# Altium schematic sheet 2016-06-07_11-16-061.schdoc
size 405 x 220 mm; SheetNumber: 1; SheetTotal: 1
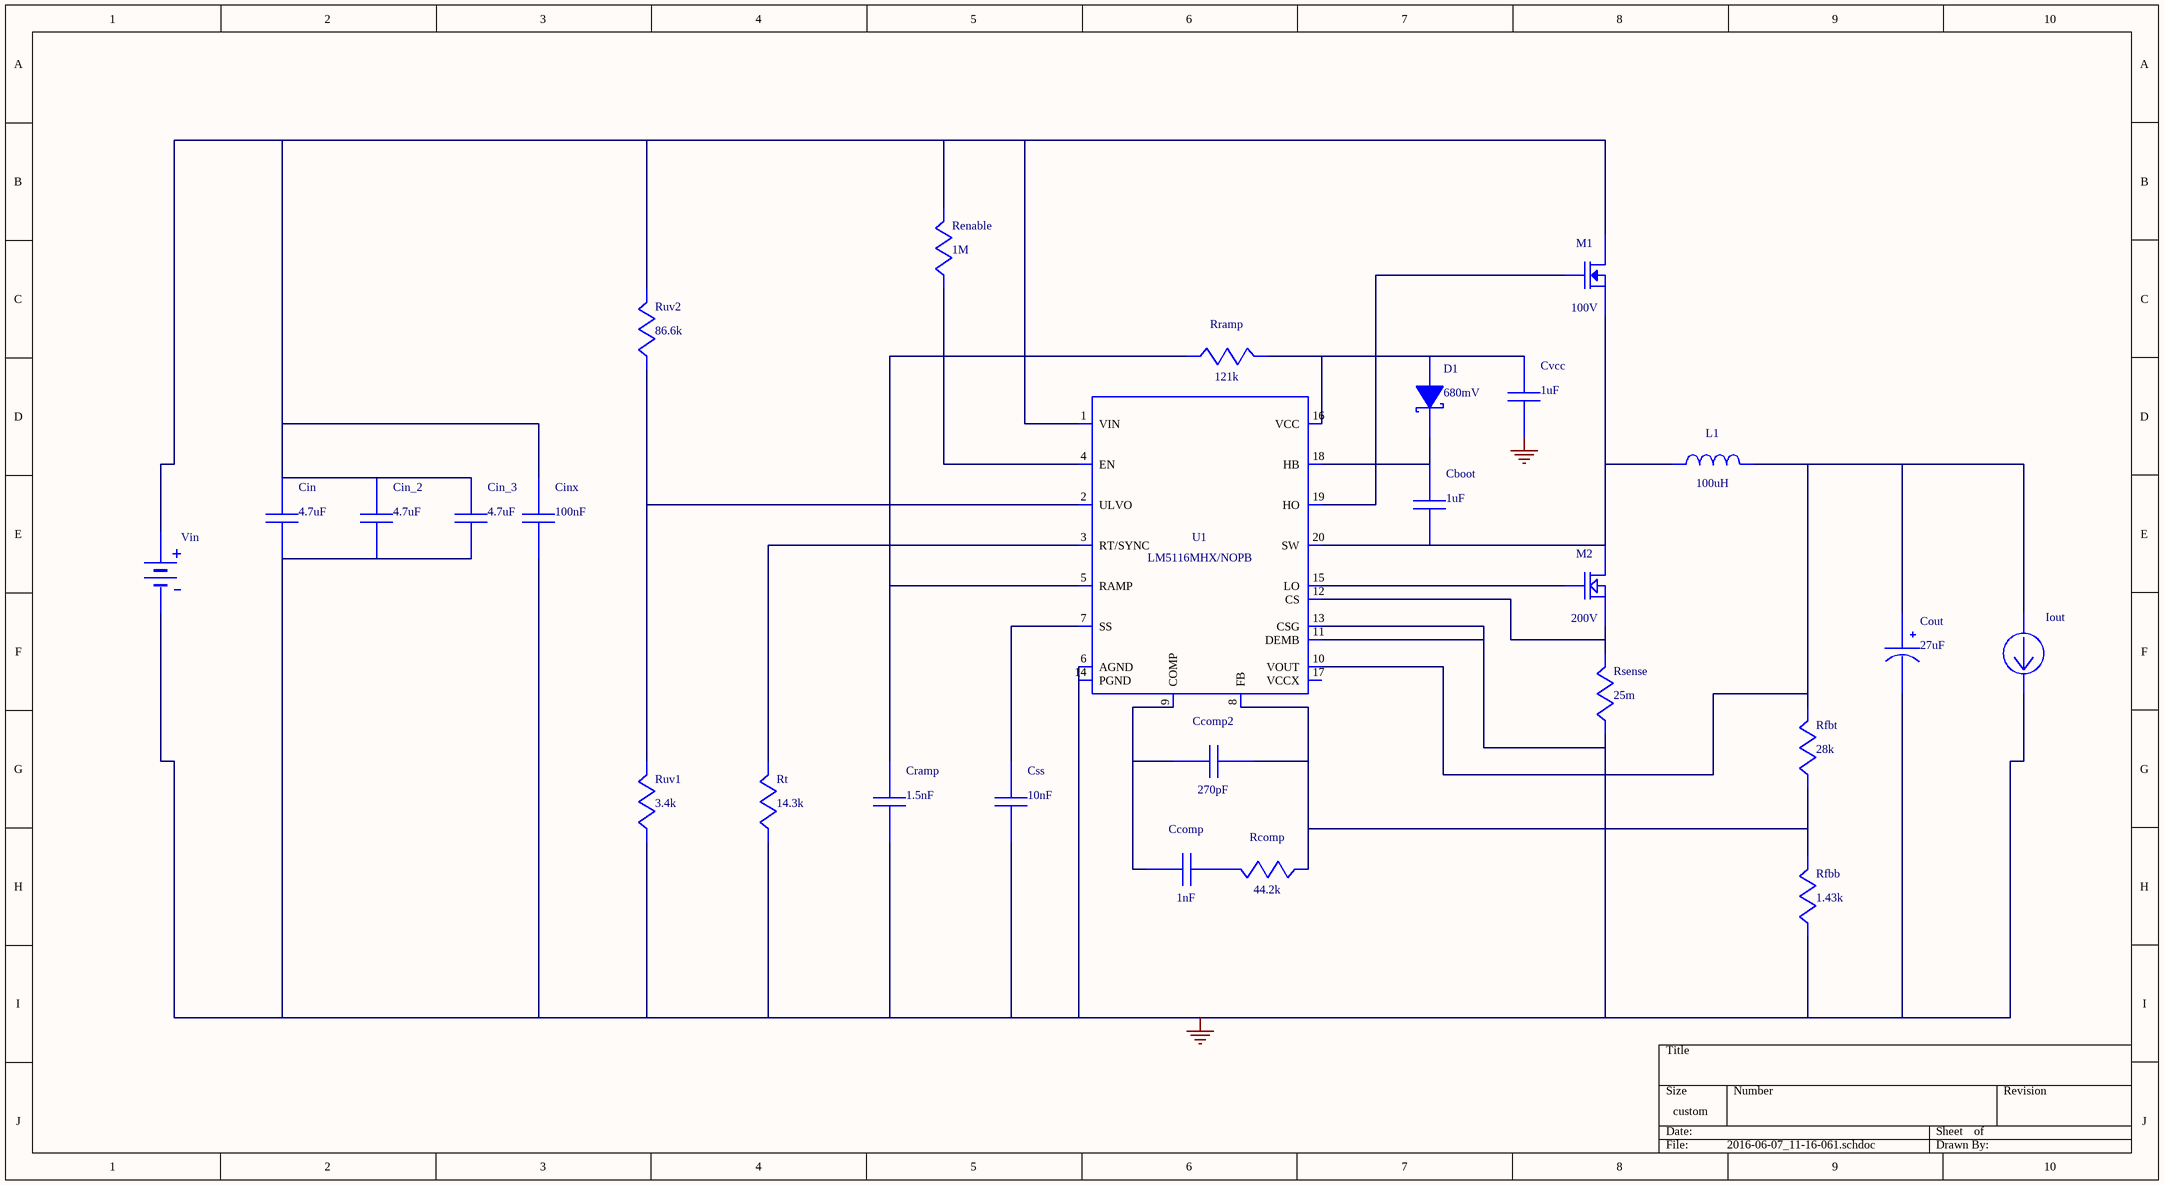
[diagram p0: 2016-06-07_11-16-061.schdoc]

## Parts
Cboot  value 1uF  (hidden comment: EMK212B7105KG-T)
Ccomp  value 1nF  (hidden comment: CL21C102JBCNFNC)
Ccomp2  value 270pF  (hidden comment: CC0805KRX7R9BB271)
Cin  value 4.7uF  (hidden comment: C3225X7S2A475M200AB)
Cin_2  value 4.7uF  (hidden comment: C3225X7S2A475M200AB)
Cin_3  value 4.7uF  (hidden comment: C3225X7S2A475M200AB)
Cinx  value 100nF  (hidden comment: HMK212B7104KG-T)
Cout  value 27uF  (hidden comment: UUD1V270MCL1GS)
Cramp  value 1.5nF  (hidden comment: CC0805KRX7R9BB152)
Css  value 10nF  (hidden comment: GRM216R71H103KA01D)
Cvcc  value 1uF  (hidden comment: EMK212B7105KG-T)
D1  value 680mV  (hidden comment: 10MQ100NTRPBF)
Iout  WB_CURRENT_LOAD  (value not drawn)
L1  value 100uH  (hidden comment: MSS1210-104KEB)
M1  value 100V  (hidden comment: CSD19534Q5A)
M2  value 200V  (hidden comment: BSC320N20NS3 G)
Rcomp  value 44.2k  (hidden comment: ERJ-6ENF4422V)
Renable  value 1M  (hidden comment: ERJ-6ENF1004V)
Rfbb  value 1.43k  (hidden comment: ERJ-6ENF1431V)
Rfbt  value 28k  (hidden comment: ERJ-6ENF2802V)
Rramp  value 121k  (hidden comment: ERJ-6ENF1213V)
Rsense  value 25m  (hidden comment: CSR1206FK25L0)
Rt  value 14.3k  (hidden comment: ERJ-6ENF1432V)
Ruv1  value 3.4k  (hidden comment: ERJ-6ENF3401V)
Ruv2  value 86.6k  (hidden comment: ERJ-6ENF8662V)
U1  LM5116MHX/NOPB
Vin  WB_BATTERY  (value not drawn)

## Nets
0: Cin.2 Cin_2.2 Cin_3.2 Cinx.2 Cout.2(-) Cramp.2 Css.2 Cvcc.2 Iout.2(-) Rfbb.2 Rsense.2 Rt.2 Ruv1.2 U1.6(AGND) U1.11(DEMB) U1.13(CSG) U1.14(PGND) U1.21(EP) Vin.2(-)
NetCboot_1: Cboot.1 D1.1(K) U1.18(HB)
NetCboot_2: Cboot.2 L1.1 M1.1(Source) M1.2(Source) M1.3(Source) M2.5(Drain) M2.6(Drain) M2.7(Drain) M2.8(Drain) M2.9(Drain) U1.20(SW)
NetCcomp2_2: Ccomp2.2 Rcomp.2 Rfbb.1 Rfbt.2 U1.8(FB)
NetCcomp_1: Ccomp.1 Ccomp2.1 U1.9(COMP)
NetCcomp_2: Ccomp.2 Rcomp.1
NetCin_1: Cin.1 Cin_2.1 Cin_3.1 Cinx.1 M1.5(Drain) M1.6(Drain) M1.7(Drain) M1.8(Drain) M1.9(Drain) Renable.1 Ruv2.1 U1.1(VIN) Vin.1(+)
NetCout_1: Cout.1(+) Iout.1(+) L1.2 Rfbt.1 U1.10(VOUT)
NetCramp_1: Cramp.1 Rramp.2 U1.5(RAMP)
NetCss_1: Css.1 U1.7(SS)
NetCvcc_1: Cvcc.1 D1.2(A) Rramp.1 U1.16(VCC)
NetM1_4: M1.4(Gate) U1.19(HO)
NetM2_1: M2.1(Source) M2.2(Source) M2.3(Source) Rsense.1 U1.12(CS)
NetM2_4: M2.4(Gate) U1.15(LO)
NetRenable_2: Renable.2 U1.4(EN)
NetRt_1: Rt.1 U1.3(RT/SYNC)
NetRuv1_1: Ruv1.1 Ruv2.2 U1.2(ULVO)

Not connected (* = marked no-connect by the designer): U1 17(VCCX)

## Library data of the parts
Cboot Cvcc = EMK212B7105KG-T: Manufacturer Name: Taiyo Yuden
Ccomp = CL21C102JBCNFNC: Manufacturer Name: Samsung Electro-Mechanics
Ccomp2 = CC0805KRX7R9BB271: CC0805KRX7R9BB27; Manufacturer Name: Yageo America
Cin Cin_2 Cin_3 = C3225X7S2A475M200AB: C3225X7S2A475M20; Manufacturer Name: TDK
Cinx = HMK212B7104KG-T: Manufacturer Name: Taiyo Yuden
Cout = UUD1V270MCL1GS: Manufacturer Name: Nichicon
Cramp = CC0805KRX7R9BB152: CC0805KRX7R9BB15; Manufacturer Name: Yageo America
Css = GRM216R71H103KA01D: GRM216R71H103KA0; Manufacturer Name: MuRata
D1 = 10MQ100NTRPBF: Manufacturer Name: International Rectifier
Iout = WB_CURRENT_LOAD: Value: UNLISTED
L1 = MSS1210-104KEB: Unknown; Manufacturer Name: Coilcraft
M1 = CSD19534Q5A: Manufacturer Name: Texas Instruments
M2 = BSC320N20NS3 G: Manufacturer Name: Infineon Technologies
Rcomp = ERJ-6ENF4422V: Manufacturer Name: Panasonic
Renable = ERJ-6ENF1004V: Manufacturer Name: Panasonic
Rfbb = ERJ-6ENF1431V: Manufacturer Name: Panasonic
Rfbt = ERJ-6ENF2802V: Manufacturer Name: Panasonic
Rramp = ERJ-6ENF1213V: Manufacturer Name: Panasonic
Rsense = CSR1206FK25L0: Manufacturer Name: Stackpole Electronics Inc
Rt = ERJ-6ENF1432V: Manufacturer Name: Panasonic
Ruv1 = ERJ-6ENF3401V: Manufacturer Name: Panasonic
Ruv2 = ERJ-6ENF8662V: Manufacturer Name: Panasonic
U1 = LM5116MHX/NOPB: Manufacturer Name: Texas Instruments; Value: UNLISTED
Vin = WB_BATTERY: Value: UNLISTED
